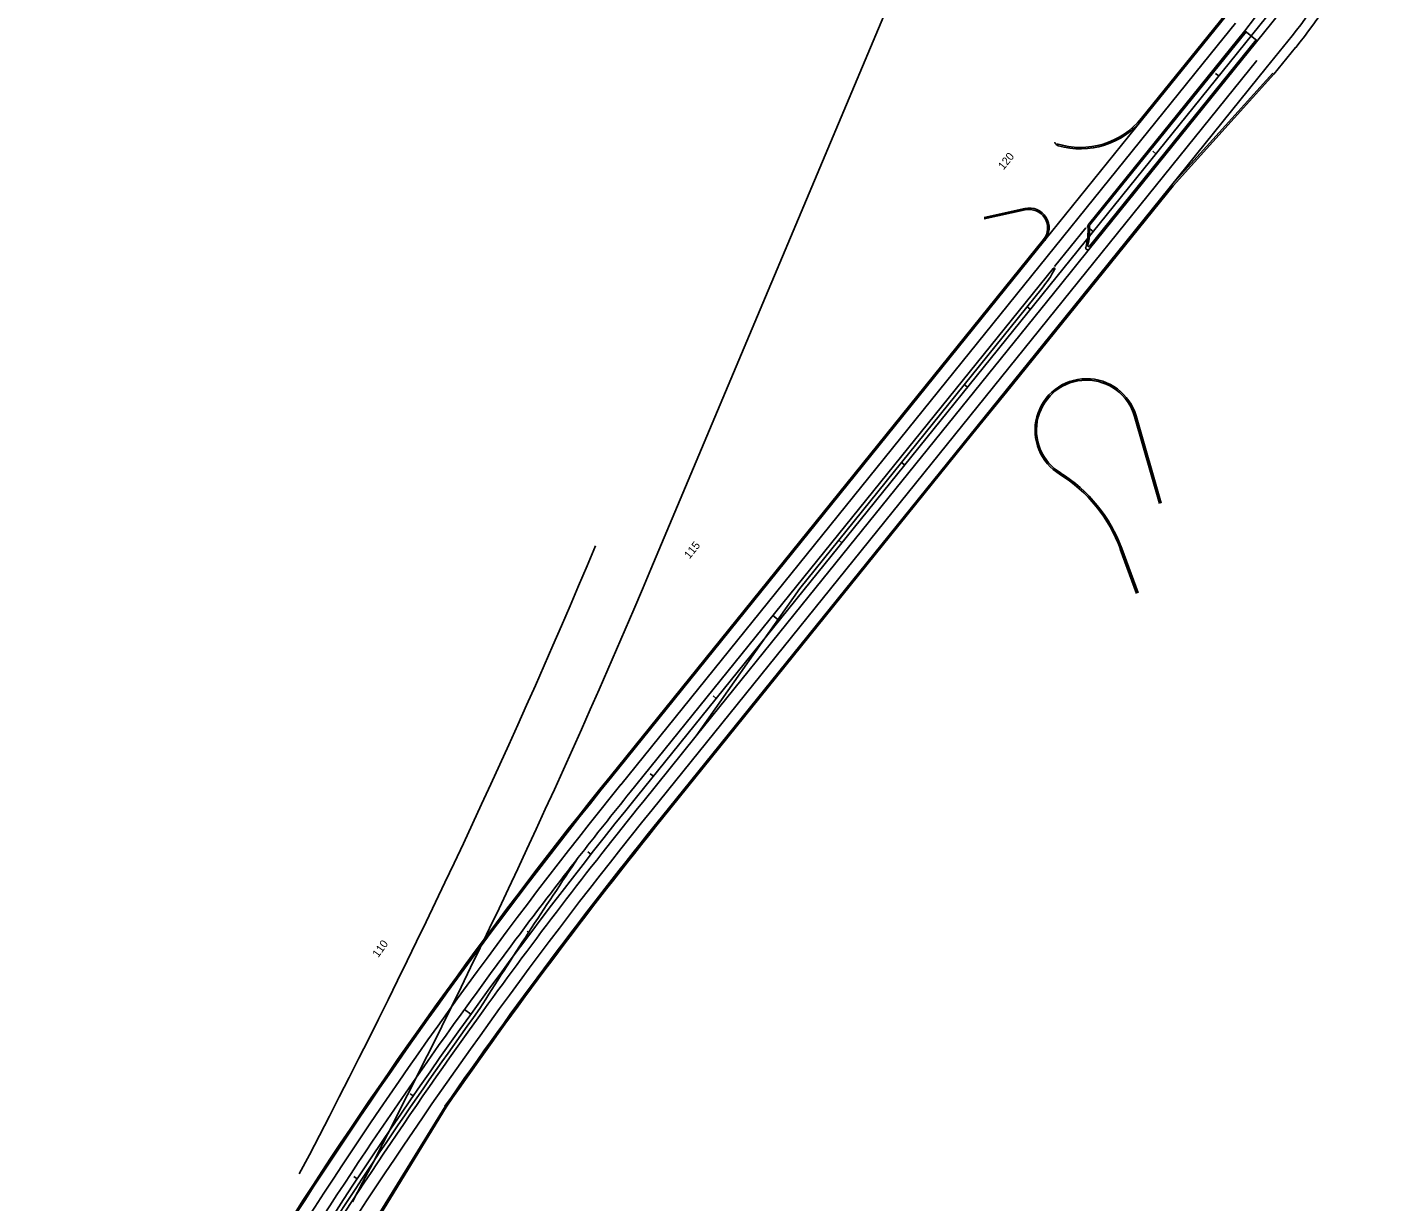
# Model space of a CAD drawing. Extents: x 2339272 to 2351734, y 366540 to 375057.
# Drawn here: x 2345450 to 2346808, y 367449 to 368623 of the extents above; entities that cross this region are included whole.
import ezdxf

# ---------------------------------------------------------------- set-up
doc = ezdxf.new("R2010")
doc.units = 0
for name, color, linetype in [('RD_HC_Cl', 7, 'Continuous'), ('RD_HC_Data_Tic', 7, 'Continuous'), ('RD_HC_TX_Sta50', 7, 'Continuous'), ('RD_PD_Final_LnLine', 7, 'Continuous'), ('RD_PD_Final_TrvlWay', 7, 'Continuous'), ('RD_PD_FOC', 7, 'Continuous'), ('RD_PD_PaveShd', 7, 'Continuous')]:
    doc.layers.add(name, color=color, linetype=linetype)

msp = doc.modelspace()

# ---------------------------------------------------------------- linework, layer by layer
at = {"layer": 'RD_HC_Cl'}
for p, q in [((2346414.9, 368892.2), (2346073.6, 368081.3)), ((2346414.9, 368892.2), (2346073.6, 368081.3)), ((2346414.9, 368892.2), (2346073.6, 368081.3)), ((2346414.9, 368892.2), (2346073.6, 368081.3)), ((2346059.3, 367853.2), (2346703.6, 368651.5)), ((2346658.3, 368627.2), (2346625.9, 368587.1)), ((2346710.6, 368609.3), (2346688.9, 368582.4))]:
    msp.add_line(p, q, dxfattribs=at)
for centre, radius, start, end in [((2346178.4, 369038.9), 684, 321.0938, 339.5935), ((2338460.5, 371285.5), 8200, 332.32074, 337.175), ((2338460.5, 371285.5), 8200, 332.32074, 337.175), ((2338460.5, 371285.5), 8200, 332.32074, 337.175), ((2338460.5, 371285.5), 8200, 332.32074, 337.175), ((2338460.5, 371285.5), 8260, 332.32074, 337.175), ((2338460.5, 371285.5), 8260, 332.32074, 337.175), ((2338460.5, 371285.5), 8260, 332.32074, 337.175), ((2338460.5, 371285.5), 8260, 332.32074, 337.175), ((2349947, 364715.5), 4996, 141.0938, 153.6971)]:
    msp.add_arc(centre, radius, start, end, dxfattribs=at)
at = {"layer": 'RD_HC_Data_Tic'}
for p, q in [((2346641.5, 368574.5), (2346638.3, 368577)), ((2346578.7, 368496.7), (2346575.5, 368499.2)), ((2346515.8, 368418.9), (2346509.6, 368423.9)), ((2346453, 368341.1), (2346449.9, 368343.6)), ((2346390.2, 368263.3), (2346387.1, 368265.8)), ((2346327.4, 368185.4), (2346324.3, 368188)), ((2346264.6, 368107.6), (2346261.5, 368110.1)), ((2346201.8, 368029.8), (2346195.6, 368034.8)), ((2346139, 367952), (2346135.9, 367954.5)), ((2346076.2, 367874.2), (2346073.1, 367876.7)), ((2346013.8, 367796), (2346010.7, 367798.5)), ((2345953, 367716.7), (2345949.8, 367719.1)), ((2345893.7, 367636.1), (2345887.2, 367640.8)), ((2345836, 367554.4), (2345832.8, 367556.7)), ((2345780, 367471.6), (2345776.7, 367473.8))]:
    msp.add_line(p, q, dxfattribs=at)
at = {"layer": 'RD_PD_Final_LnLine'}
for p, q in [((2346648.9, 368634.7), (2346565.4, 368531.3)), ((2346648.4, 368615), (2346043.7, 367865.7)), ((2346710.6, 368609.3), (2346688.9, 368582.4)), ((2346679.6, 368589.9), (2346074.8, 367840.6)), ((2346688.9, 368582.4), (2346487.8, 368333.2)), ((2346594.7, 368465.7), (2346695.6, 368577.1)), ((2346467.4, 368409.9), (2346565.4, 368531.3)), ((2346406.8, 368432.9), (2346447.5, 368441.9)), ((2346508.7, 368422.7), (2346477.2, 368383.8)), ((2346467.4, 368409.9), (2346034.4, 367873.3)), ((2346483.2, 368365.7), (2346511.9, 368401.3)), ((2346483.2, 368365.7), (2346232, 368054.4)), ((2346487.8, 368333.2), (2346084.2, 367833.1)), ((2346118.9, 367914.4), (2346232, 368054.4)), ((2345789.2, 367416.2), (2345867.8, 367544))]:
    msp.add_line(p, q, dxfattribs=at)
for centre, radius, start, end in [((2346503.2, 368581.5), 80, 253.9065, 321.0938), ((2346482.4, 368509.5), 5, 195.865, 253.9065), ((2346451.9, 368422.4), 20, 321.0938, 102.484), ((2349947, 364715.5), 5028, 141.0938, 153.3996), ((2349947, 364715.5), 5016, 141.0938, 153.4055), ((2349947, 364715.5), 4976, 141.0938, 153.4002), ((2349947, 364715.5), 4964, 141.0938, 145.2627), ((2349947, 364715.5), 5004, 142.0511, 144.1409), ((2349947, 364715.5), 5004, 144.1409, 148.8707)]:
    msp.add_arc(centre, radius, start, end, dxfattribs=at)
at = {"layer": 'RD_PD_Final_TrvlWay'}
for p, q in [((2346709.8, 368646.5), (2346511.9, 368401.3)), ((2346667.6, 368619.7), (2346511.2, 368425.8)), ((2346475.8, 368382), (2346053.1, 367858.2)), ((2346465, 368362.3), (2346222.6, 368062)), ((2346557.3, 368234), (2346582.3, 368146.8)), ((2346544.6, 368101.8), (2346560.8, 368057.4)), ((2346222.6, 368062), (2346118.9, 367914.4)), ((2346065.5, 367848.2), (2346118.9, 367914.4))]:
    msp.add_line(p, q, dxfattribs=at)
for centre, radius, start, end in [((2346182, 369011.6), 624, 321.0938, 53.1918), ((2346448.3, 368420.3), 62.6, 343.9661, 3.6972), ((2346512.7, 368424.6), 2, 141.0938, 186.6668), ((2346510.4, 368402.6), 2, 166.9357, 321.0938), ((2346365.5, 368442.2), 127.6, 321.2453, 331.2935), ((2346476.6, 368381.4), 1, 331.2935, 141.0938), ((2346509.3, 368220.2), 50, 15.9925, 239.3979), ((2346403.7, 368050.3), 150, 20.0868, 58.132), ((2349947, 364715.5), 5004, 141.0938, 142.0511), ((2349947, 364715.5), 4988, 141.0938, 144.1121), ((2350128, 364994.9), 4985.9, 145.8645, 147.9351), ((2349947, 364715.5), 4988, 144.1121, 148.3622), ((2349947, 364715.5), 4992, 144.1121, 148.1246)]:
    msp.add_arc(centre, radius, start, end, dxfattribs=at)
at = {"layer": 'RD_PD_FOC'}
for p, q in [((2346647.8, 368635.7), (2346564.3, 368532.2)), ((2346678.9, 368610.5), (2346512.3, 368404.1)), ((2346668.8, 368618.7), (2346512.7, 368425.4)), ((2346595.9, 368464.7), (2346696.7, 368576.1)), ((2346595.9, 368464.7), (2346429.2, 368258.2)), ((2346407.1, 368431.5), (2346447.9, 368440.5)), ((2346466.3, 368410.8), (2346033.2, 367874.2)), ((2346429.2, 368258.2), (2346395.4, 368216.4)), ((2346558.8, 368234.4), (2346583.8, 368147.2)), ((2346395.4, 368216.4), (2346085.3, 367832.1)), ((2346543.1, 368101.3), (2346559.4, 368056.8)), ((2345790.5, 367415.4), (2345869, 367543.2))]:
    msp.add_line(p, q, dxfattribs=at)
for centre, radius, start, end in [((2346503.2, 368581.5), 78.5, 252.3972, 321.0938), ((2346451.9, 368422.4), 18.5, 321.0938, 102.484), ((2346448.3, 368420.3), 64.1, 346.1411, 3.2809), ((2346514.3, 368424.1), 2, 141.0938, 183.2809), ((2346511.5, 368404.7), 1, 166.1411, 321.0938), ((2346509.3, 368220.2), 51.5, 15.9925, 239.3979), ((2346403.7, 368050.3), 148.5, 20.0868, 58.132), ((2349947, 364715.5), 5029.5, 141.0938, 153.3986), ((2349947, 364715.5), 4962.5, 141.0938, 145.2627)]:
    msp.add_arc(centre, radius, start, end, dxfattribs=at)
at = {"layer": 'RD_PD_PaveShd'}
for p, q in [((2346667.6, 368619.7), (2346680, 368609.6)), ((2346718.4, 368603), (2346696.7, 368576.1))]:
    msp.add_line(p, q, dxfattribs=at)
msp.add_arc((2346178.4, 369038.9), 694, 321.0938, 339.5935, dxfattribs=at)

# ---------------------------------------------------------------- texts
at = {"layer": 'RD_HC_TX_Sta50'}
for s, rotation, p in [('120', 51.0938, (2346426.3, 368479.9)), ('115', 51.0938, (2346112.3, 368090.9)), ('110', 54.2249, (2345801, 367692.2))]:
    msp.add_text(s, height=8, rotation=rotation, dxfattribs=at).set_placement(p)

doc.saveas('drawing.dxf')
